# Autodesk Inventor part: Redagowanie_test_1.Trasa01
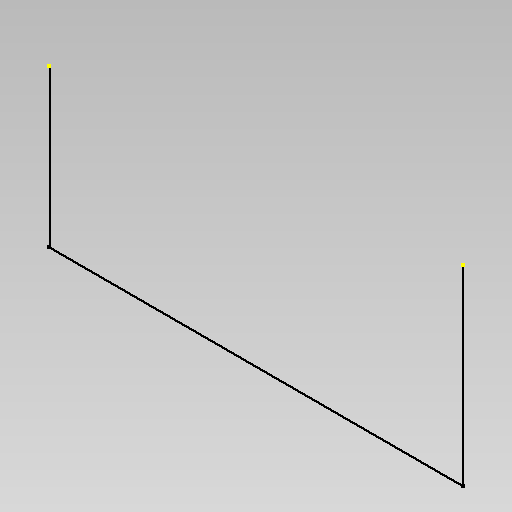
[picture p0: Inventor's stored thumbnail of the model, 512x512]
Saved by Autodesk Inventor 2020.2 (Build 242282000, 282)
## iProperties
StyleName: _Piping Style 48
Manager: www.cadconsulting.pl
Company: Fabian Stasiak CAD Consulting
Name: ISO 2531 - Rury żelazne kołnierzowe i łączniki
ActiveState: True
PipeType: Rigid Pipe
Material: UnInitValue
Standard: UnInitValue
FittingMaterial: UnInitValue
FittingStandard: UnInitValue
RouteDirection90: True
RouteDirection45: True
IsFlanged: False
IsButtWelded: False
DiameterType: Nominal
Diameter: M40
Schedule: PN10
OD: UnInitValue
ID: UnInitValue
Ending: UnInitValue
IntermediateSegmentsMin: 1000,000 mm
IntermediateSegmentsMax: 9000,000 mm
IntermediateSegmentsInc: 10,000 mm
TerminationSegmentsMin: 1000,000 mm
TerminationSegmentsMax: 9000,000 mm
TerminationSegmentsInc: 10,000 mm
RoundUpValue: UnInitValue
PipingComponentColor: As Material
PipeKey: v3#f52fbdcb-ece8-4303-8b76-5dbe8c7f2f9c#16
Elbow90Key: v3#451ae64e-c79d-4cba-b533-c09b8090ecb2#1
Elbow45Key: v3#81684a3f-f2a4-4fe6-95b1-f067ddead22f#1
GasketKey: UnInitValue
FlangeKey: UnInitValue
_ComponentInfo: <CS><C N="Pipe" R="2.700000" IR="2.000000" PL="PL" PN="ISO 2531 Pipe with Integrally Cast Flanges DN40 PN 10"><CO N="1"><FE V="0"/><FD V="0"/><ET V="Flanged"/><
Gap: UnInitValue
ShowGap: UnInitValue
MixedUnits: False
UseFlangsForCouplings: UnInitValue
IsSelfDraining: False
ElbowCustomKey: UnInitValue
_PSKETCH_SNAP: False
_PSKETCH_RSNP: False
_BASENETWORK_NOTAUTODIMENSION: False
Created: 2014-08
Part Number: Redagowanie_test_1.Trasa01
Material: Ogólny
Document SubType Name: Modeling
Designer: F.Stasiak
Density: 1 g/cm^3
Appearance: Domyślna
Catalog Web Link: www.expertbooks.pl
Author: F.Stasiak
Subject: Zbiór ćwiczeń. Autodesk Inventor 2020. Kurs Professional
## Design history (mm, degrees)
node "Punkt konstrukcyjny1"
node "Punkt konstrukcyjny2"
sketch "Szkic 3D1"
